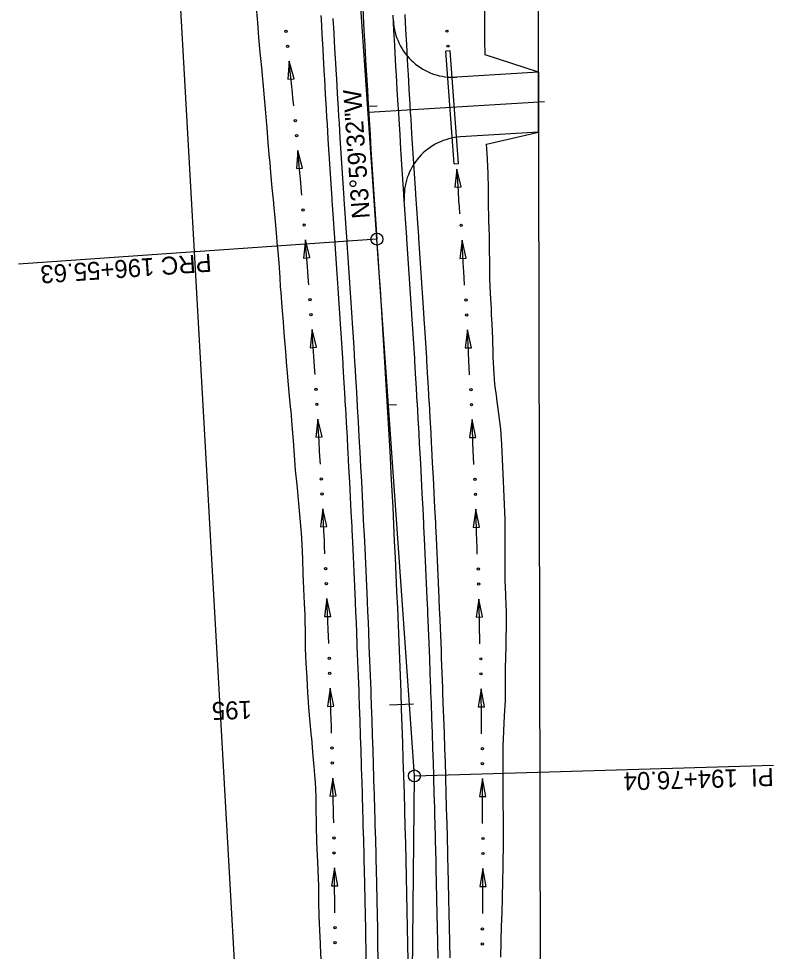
# Model space of a CAD drawing. Extents: x 1 to 1477871, y 1 to 1872901.
# Drawn here: x 1438502.6 to 1438754.8, y 1869354.3 to 1869665.9 of the extents above; entities that cross this region are included whole.
import ezdxf

# ---------------------------------------------------------------- set-up
doc = ezdxf.new("R2010")
doc.units = 0
for name, color, linetype in [('R_Drive', 7, 'Continuous'), ('R_Horz Alg', 7, 'Continuous'), ('R_Horz Alg Annot', 7, 'Continuous'), ('R_No Plot', 7, 'Continuous'), ('R_Proposed Const Limits_Cut', 7, 'Continuous'), ('R_Proposed Road_Lane', 7, 'Continuous'), ('R_Proposed Road_Shoulder', 7, 'Continuous'), ('R_ROW', 7, 'Continuous'), ('R_Water', 7, 'Continuous')]:
    doc.layers.add(name, color=color, linetype=linetype)

msp = doc.modelspace()

# ---------------------------------------------------------------- linework, layer by layer
at = {"layer": 'R_Drive'}
for p, q in [((1438676.27, 1869647.97), (1438648.98, 1869646.32)), ((1438676.27, 1869647.97), (1438676.31, 1869627.94)), ((1438676.31, 1869627.94), (1438650.21, 1869626.36))]:
    msp.add_line(p, q, dxfattribs=at)
for centre, start, end in [((1438647.77, 1869666.28), 183.2722, 273.4625), ((1438651.41, 1869606.39), 93.4625, 183.7812)]:
    msp.add_arc(centre, 20, start, end, dxfattribs=at)
at = {"layer": 'R_Horz Alg'}
for centre, start, end in [((1443194.86, 1869911.35), 180, 183.99213), ((1434049.78, 1869273.13), 359.5, 3.99213)]:
    msp.add_arc(centre, 4583.66, start, end, dxfattribs=at)
at = {"layer": 'R_Horz Alg Annot'}
for p, q in [((1438622.32, 1869592.24), (1438611.19, 1869751.6)), ((1438634.83, 1869412.9), (1438622.32, 1869592.24)), ((1438633.26, 1869233.13), (1438634.83, 1869412.9))]:
    msp.add_line(p, q, dxfattribs=at)
for points in [[(1438622.44, 1869636.7), (1438619.44, 1869636.52)], [(1438622.32, 1869592.24), (1438502.61, 1869583.89)], [(1438628.85, 1869536.9), (1438625.85, 1869536.72)], [(1438626.52, 1869436.69), (1438634.51, 1869436.98)], [(1438634.83, 1869412.9), (1438754.78, 1869416.56)]]:
    msp.add_lwpolyline(points, dxfattribs=at)
for centre in [(1438622.32, 1869592.24), (1438634.83, 1869412.9)]:
    msp.add_circle(centre, 2, dxfattribs=at)
at = {"layer": 'R_No Plot'}
msp.add_line((1438678.33, 1869638.08), (1438619.56, 1869634.52), dxfattribs=at)
at = {"layer": 'R_Proposed Const Limits_Cut'}
for points in [[(1438603.7, 1869351.37), (1438603.47, 1869356.33), (1438603.43, 1869356.98), (1438603.23, 1869361.3), (1438603.03, 1869366.26), (1438602.95, 1869370.71), (1438602.95, 1869371.23), (1438602.86, 1869376.2), (1438602.73, 1869381.16), (1438602.56, 1869384.44), (1438602.47, 1869386.12), (1438602.19, 1869391.09), (1438602.09, 1869396.05), (1438602.08, 1869398.16), (1438602.07, 1869401.02), (1438602.04, 1869405.99), (1438601.75, 1869410.95), (1438601.66, 1869411.89), (1438601.34, 1869415.91), (1438600.95, 1869420.87), (1438600.52, 1869425.59), (1438600.49, 1869425.82), (1438599.99, 1869430.77), (1438599.6, 1869435.73), (1438599.35, 1869439.29), (1438599.27, 1869440.69), (1438599, 1869445.65), (1438598.72, 1869450.61), (1438598.59, 1869453), (1438598.47, 1869455.56), (1438598.4, 1869460.53), (1438598.39, 1869465.5), (1438598.39, 1869466.73), (1438598.17, 1869470.46), (1438597.9, 1869475.42), (1438597.72, 1869480.39), (1438597.71, 1869480.44), (1438597.53, 1869485.35), (1438597.33, 1869490.31), (1438597.08, 1869494.15), (1438596.99, 1869495.27), (1438596.56, 1869500.22), (1438596.1, 1869505.17), (1438595.85, 1869507.84), (1438595.63, 1869510.11), (1438595.15, 1869515.06), (1438594.76, 1869520.01), (1438594.65, 1869521.52), (1438594.4, 1869524.97), (1438594.04, 1869529.92), (1438593.61, 1869534.87), (1438593.58, 1869535.21), (1438593.14, 1869539.81), (1438592.66, 1869544.76), (1438592.3, 1869548.88), (1438592.24, 1869549.71), (1438591.86, 1869554.66), (1438591.47, 1869559.6), (1438591.24, 1869562.56), (1438591.08, 1869564.55), (1438590.69, 1869569.5), (1438590.28, 1869574.45), (1438590.14, 1869576.24), (1438590, 1869579.41), (1438589.66, 1869584.36), (1438589.19, 1869589.3), (1438589.14, 1869589.93), (1438588.73, 1869594.31), (1438588.27, 1869599.33), (1438587.87, 1869603.86), (1438587.83, 1869604.34), (1438587.37, 1869609.36), (1438586.91, 1869614.38), (1438586.6, 1869617.79), (1438586.46, 1869619.4), (1438586.03, 1869624.42), (1438585.6, 1869629.44), (1438585.41, 1869631.74), (1438585.18, 1869634.46), (1438584.75, 1869639.48), (1438584.31, 1869644.5), (1438584.21, 1869645.68), (1438583.85, 1869649.52), (1438583.36, 1869654.54), (1438582.9, 1869659.56), (1438582.89, 1869659.62), (1438582.47, 1869664.58), (1438582.38, 1869665.77), (1438582.07, 1869669.61)], [(1438663.74, 1869352.4), (1438663.85, 1869357.43), (1438663.86, 1869358.1), (1438663.96, 1869362.47), (1438664.12, 1869367.51), (1438664.25, 1869372.02), (1438664.26, 1869372.55), (1438664.39, 1869377.59), (1438664.49, 1869382.63), (1438664.55, 1869385.95), (1438664.58, 1869387.67), (1438664.64, 1869392.71), (1438664.59, 1869397.74), (1438664.56, 1869399.88), (1438664.53, 1869402.78), (1438664.47, 1869407.81), (1438664.48, 1869412.85), (1438664.48, 1869413.8), (1438664.48, 1869417.89), (1438664.48, 1869422.93), (1438664.73, 1869427.74), (1438664.74, 1869427.98), (1438664.99, 1869433.03), (1438665.25, 1869438.08), (1438665.25, 1869441.69), (1438665.25, 1869443.12), (1438665.25, 1869448.16), (1438665.37, 1869453.21), (1438665.47, 1869455.64), (1438665.5, 1869458.25), (1438665.57, 1869463.3), (1438665.58, 1869468.34), (1438665.54, 1869469.59), (1438665.41, 1869473.38), (1438665.22, 1869478.42), (1438665.13, 1869483.46), (1438665.12, 1869483.51), (1438665.16, 1869488.51), (1438665.2, 1869493.55), (1438665.22, 1869497.47), (1438665.17, 1869498.6), (1438664.95, 1869503.63), (1438664.72, 1869508.67), (1438664.59, 1869511.39), (1438664.49, 1869513.7), (1438664.27, 1869518.74), (1438664.03, 1869523.78), (1438663.96, 1869525.31), (1438663.69, 1869528.8), (1438663.03, 1869533.82), (1438662.38, 1869538.83), (1438662.33, 1869539.17), (1438661.67, 1869543.83), (1438661.33, 1869548.86), (1438661.15, 1869553.06), (1438661.13, 1869553.9), (1438661.02, 1869558.94), (1438660.83, 1869563.98), (1438660.65, 1869566.99), (1438660.56, 1869569.01), (1438660.31, 1869574.05), (1438660.06, 1869579.08), (1438660.03, 1869580.91), (1438659.99, 1869584.13), (1438659.93, 1869589.18), (1438659.88, 1869594.23), (1438659.87, 1869594.86), (1438659.73, 1869599.2), (1438659.57, 1869604.16), (1438659.58, 1869608.65), (1438659.58, 1869609.13), (1438659.48, 1869614.09), (1438659.28, 1869619.04), (1438659, 1869622.41), (1438658.88, 1869623.99), (1438676.31, 1869627.94), (1438676.27, 1869647.97), (1438658.5, 1869653.76), (1438658.33, 1869658.71), (1438658.35, 1869663.68), (1438658.35, 1869663.74), (1438658.32, 1869668.64)]]:
    msp.add_lwpolyline(points, dxfattribs=at)
at = {"layer": 'R_Proposed Road_Lane'}
for points in [[(1438622.76, 1869351.69), (1438622.67, 1869356.68), (1438622.66, 1869357.34), (1438622.58, 1869361.67), (1438622.48, 1869366.66), (1438622.39, 1869371.13), (1438622.38, 1869371.65), (1438622.27, 1869376.63), (1438622.15, 1869381.62), (1438622.07, 1869384.92), (1438622.03, 1869386.61), (1438621.9, 1869391.6), (1438621.77, 1869396.58), (1438621.71, 1869398.7), (1438621.63, 1869401.57), (1438621.49, 1869406.56), (1438621.34, 1869411.55), (1438621.31, 1869412.49), (1438621.19, 1869416.53), (1438621.03, 1869421.52), (1438620.87, 1869426.27), (1438620.86, 1869426.51), (1438620.7, 1869431.49), (1438620.52, 1869436.48), (1438620.39, 1869440.06), (1438620.34, 1869441.46), (1438620.15, 1869446.45), (1438619.96, 1869451.43), (1438619.87, 1869453.84), (1438619.76, 1869456.42), (1438619.56, 1869461.4), (1438619.35, 1869466.39), (1438619.3, 1869467.62), (1438619.14, 1869471.37), (1438618.92, 1869476.36), (1438618.7, 1869481.34), (1438618.69, 1869481.4), (1438618.47, 1869486.33), (1438618.23, 1869491.31), (1438618.04, 1869495.17), (1438617.99, 1869496.29), (1438617.74, 1869501.28), (1438617.49, 1869506.26), (1438617.35, 1869508.95), (1438617.24, 1869511.24), (1438616.97, 1869516.22), (1438616.7, 1869521.21), (1438616.62, 1869522.72), (1438616.43, 1869526.19), (1438616.15, 1869531.17), (1438615.87, 1869536.15), (1438615.85, 1869536.49), (1438615.58, 1869541.13), (1438615.28, 1869546.11), (1438615.03, 1869550.26), (1438614.98, 1869551.09), (1438614.68, 1869556.07), (1438614.37, 1869561.05), (1438614.18, 1869564.02), (1438614.05, 1869566.03), (1438613.73, 1869571.01), (1438613.4, 1869575.99), (1438613.28, 1869577.79), (1438613.07, 1869580.96), (1438612.73, 1869585.94), (1438612.38, 1869590.92), (1438612.34, 1869591.54), (1438612.04, 1869595.91), (1438611.7, 1869600.91), (1438611.39, 1869605.43), (1438611.36, 1869605.91), (1438611.03, 1869610.91), (1438610.7, 1869615.91), (1438610.49, 1869619.31), (1438610.39, 1869620.91), (1438610.07, 1869625.92), (1438609.76, 1869630.92), (1438609.62, 1869633.2), (1438609.46, 1869635.92), (1438609.16, 1869640.92), (1438608.87, 1869645.92), (1438608.8, 1869647.1), (1438608.58, 1869650.93), (1438608.3, 1869655.93), (1438608.03, 1869660.93), (1438608.02, 1869660.99), (1438607.75, 1869665.94)], [(1438642.76, 1869352.04), (1438642.67, 1869357.05), (1438642.66, 1869357.71), (1438642.58, 1869362.06), (1438642.48, 1869367.07), (1438642.38, 1869371.55), (1438642.37, 1869372.08), (1438642.26, 1869377.09), (1438642.14, 1869382.1), (1438642.06, 1869385.4), (1438642.02, 1869387.11), (1438641.9, 1869392.11), (1438641.76, 1869397.12), (1438641.71, 1869399.25), (1438641.62, 1869402.13), (1438641.48, 1869407.14), (1438641.33, 1869412.15), (1438641.3, 1869413.1), (1438641.18, 1869417.16), (1438641.02, 1869422.17), (1438640.86, 1869426.94), (1438640.85, 1869427.18), (1438640.68, 1869432.18), (1438640.51, 1869437.19), (1438640.38, 1869440.79), (1438640.32, 1869442.2), (1438640.14, 1869447.21), (1438639.95, 1869452.21), (1438639.85, 1869454.63), (1438639.75, 1869457.22), (1438639.54, 1869462.23), (1438639.33, 1869467.23), (1438639.28, 1869468.47), (1438639.12, 1869472.24), (1438638.9, 1869477.25), (1438638.68, 1869482.25), (1438638.67, 1869482.31), (1438638.44, 1869487.26), (1438638.21, 1869492.26), (1438638.02, 1869496.14), (1438637.97, 1869497.27), (1438637.72, 1869502.27), (1438637.47, 1869507.28), (1438637.33, 1869509.98), (1438637.21, 1869512.28), (1438636.94, 1869517.29), (1438636.68, 1869522.29), (1438636.59, 1869523.81), (1438636.4, 1869527.29), (1438636.12, 1869532.3), (1438635.83, 1869537.3), (1438635.81, 1869537.64), (1438635.54, 1869542.3), (1438635.25, 1869547.3), (1438635, 1869551.47), (1438634.95, 1869552.3), (1438634.64, 1869557.31), (1438634.33, 1869562.31), (1438634.14, 1869565.29), (1438634.01, 1869567.31), (1438633.68, 1869572.31), (1438633.35, 1869577.31), (1438633.24, 1869579.12), (1438633.02, 1869582.31), (1438632.68, 1869587.31), (1438632.33, 1869592.31), (1438632.29, 1869592.94), (1438631.99, 1869597.29), (1438631.65, 1869602.27), (1438631.35, 1869606.76), (1438631.31, 1869607.24), (1438630.99, 1869612.22), (1438630.66, 1869617.2), (1438630.45, 1869620.59), (1438630.34, 1869622.18), (1438630.03, 1869627.16), (1438629.73, 1869632.14), (1438629.59, 1869634.42), (1438629.42, 1869637.12), (1438629.13, 1869642.1), (1438628.83, 1869647.08), (1438628.77, 1869648.25), (1438628.55, 1869652.06), (1438628.27, 1869657.04), (1438628, 1869662.02), (1438627.99, 1869662.08), (1438627.73, 1869667)]]:
    msp.add_lwpolyline(points, dxfattribs=at)
at = {"layer": 'R_Proposed Road_Shoulder'}
for points in [[(1438618.76, 1869351.62), (1438618.67, 1869356.61), (1438618.66, 1869357.26), (1438618.58, 1869361.59), (1438618.48, 1869366.58), (1438618.39, 1869371.04), (1438618.38, 1869371.56), (1438618.27, 1869376.54), (1438618.15, 1869381.53), (1438618.07, 1869384.82), (1438618.03, 1869386.51), (1438617.9, 1869391.49), (1438617.77, 1869396.48), (1438617.71, 1869398.59), (1438617.64, 1869401.46), (1438617.49, 1869406.44), (1438617.34, 1869411.43), (1438617.31, 1869412.37), (1438617.19, 1869416.41), (1438617.03, 1869421.39), (1438616.88, 1869426.14), (1438616.87, 1869426.37), (1438616.7, 1869431.35), (1438616.52, 1869436.33), (1438616.39, 1869439.91), (1438616.34, 1869441.32), (1438616.16, 1869446.3), (1438615.96, 1869451.28), (1438615.87, 1869453.68), (1438615.77, 1869456.26), (1438615.56, 1869461.24), (1438615.36, 1869466.22), (1438615.3, 1869467.45), (1438615.14, 1869471.2), (1438614.92, 1869476.18), (1438614.7, 1869481.16), (1438614.7, 1869481.21), (1438614.47, 1869486.14), (1438614.24, 1869491.12), (1438614.05, 1869494.98), (1438613.99, 1869496.1), (1438613.75, 1869501.08), (1438613.5, 1869506.05), (1438613.36, 1869508.74), (1438613.24, 1869511.03), (1438612.98, 1869516.01), (1438612.71, 1869520.99), (1438612.63, 1869522.5), (1438612.44, 1869525.97), (1438612.16, 1869530.94), (1438611.88, 1869535.92), (1438611.85, 1869536.26), (1438611.58, 1869540.9), (1438611.29, 1869545.87), (1438611.04, 1869550.02), (1438610.99, 1869550.85), (1438610.69, 1869555.82), (1438610.37, 1869560.8), (1438610.19, 1869563.77), (1438610.06, 1869565.77), (1438609.74, 1869570.75), (1438609.41, 1869575.72), (1438609.29, 1869577.52), (1438609.07, 1869580.69), (1438608.74, 1869585.67), (1438608.39, 1869590.64), (1438608.35, 1869591.27), (1438608.05, 1869595.64), (1438607.71, 1869600.64), (1438607.4, 1869605.16), (1438607.37, 1869605.65), (1438607.04, 1869610.65), (1438606.71, 1869615.66), (1438606.49, 1869619.06), (1438606.39, 1869620.66), (1438606.08, 1869625.67), (1438605.77, 1869630.67), (1438605.63, 1869632.96), (1438605.47, 1869635.68), (1438605.17, 1869640.69), (1438604.88, 1869645.69), (1438604.81, 1869646.87), (1438604.59, 1869650.7), (1438604.31, 1869655.71), (1438604.03, 1869660.71), (1438604.03, 1869660.77), (1438603.76, 1869665.72), (1438603.7, 1869666.9)], [(1438646.76, 1869352.11), (1438646.67, 1869357.12), (1438646.66, 1869357.78), (1438646.57, 1869362.14), (1438646.48, 1869367.15), (1438646.38, 1869371.64), (1438646.37, 1869372.16), (1438646.26, 1869377.18), (1438646.14, 1869382.19), (1438646.06, 1869385.5), (1438646.02, 1869387.21), (1438645.89, 1869392.22), (1438645.76, 1869397.23), (1438645.7, 1869399.36), (1438645.62, 1869402.25), (1438645.48, 1869407.26), (1438645.33, 1869412.27), (1438645.3, 1869413.22), (1438645.18, 1869417.29), (1438645.02, 1869422.3), (1438644.86, 1869427.08), (1438644.85, 1869427.31), (1438644.68, 1869432.32), (1438644.5, 1869437.33), (1438644.37, 1869440.93), (1438644.32, 1869442.35), (1438644.14, 1869447.36), (1438643.94, 1869452.37), (1438643.85, 1869454.79), (1438643.74, 1869457.38), (1438643.54, 1869462.39), (1438643.33, 1869467.4), (1438643.28, 1869468.64), (1438643.12, 1869472.41), (1438642.9, 1869477.42), (1438642.67, 1869482.44), (1438642.67, 1869482.49), (1438642.44, 1869487.45), (1438642.2, 1869492.45), (1438642.02, 1869496.34), (1438641.96, 1869497.46), (1438641.71, 1869502.47), (1438641.46, 1869507.48), (1438641.32, 1869510.19), (1438641.2, 1869512.49), (1438640.94, 1869517.5), (1438640.67, 1869522.51), (1438640.59, 1869524.03), (1438640.39, 1869527.51), (1438640.11, 1869532.52), (1438639.83, 1869537.53), (1438639.81, 1869537.87), (1438639.54, 1869542.54), (1438639.24, 1869547.54), (1438638.99, 1869551.71), (1438638.94, 1869552.55), (1438638.63, 1869557.55), (1438638.32, 1869562.56), (1438638.13, 1869565.55), (1438638, 1869567.56), (1438637.68, 1869572.57), (1438637.35, 1869577.57), (1438637.23, 1869579.38), (1438637.01, 1869582.58), (1438636.67, 1869587.58), (1438636.32, 1869592.58), (1438636.28, 1869593.22), (1438635.98, 1869597.56), (1438635.64, 1869602.54), (1438635.34, 1869607.03), (1438635.31, 1869607.51), (1438634.98, 1869612.48), (1438634.65, 1869617.46), (1438634.44, 1869620.84), (1438634.34, 1869622.43), (1438634.02, 1869627.41), (1438633.72, 1869632.38), (1438633.58, 1869634.66), (1438633.42, 1869637.36), (1438633.12, 1869642.33), (1438632.83, 1869647.31), (1438632.76, 1869648.48), (1438632.54, 1869652.29), (1438632.26, 1869657.26), (1438631.99, 1869662.24), (1438631.99, 1869662.3), (1438631.72, 1869667.22)]]:
    msp.add_lwpolyline(points, dxfattribs=at)
at = {"layer": 'R_ROW'}
for p, q in [((1438587.34, 1869127.27), (1438531.34, 1870121.98)), ((1438676.17, 1869699.24), (1438677.33, 1869126.48))]:
    msp.add_line(p, q, dxfattribs=at)
at = {"layer": 'R_Water'}
for p, q in [((1438646.83, 1869655.1), (1438645.33, 1869654.99)), ((1438648.11, 1869617.41), (1438645.33, 1869654.99)), ((1438649.61, 1869617.52), (1438646.83, 1869655.1)), ((1438593.01, 1869651.7), (1438592.56, 1869645.62)), ((1438594.67, 1869645.83), (1438593.01, 1869651.7)), ((1438592.56, 1869645.62), (1438594.67, 1869645.83)), ((1438595.93, 1869621.84), (1438595.39, 1869615.77)), ((1438597.5, 1869615.95), (1438595.93, 1869621.84)), ((1438595.39, 1869615.77), (1438597.5, 1869615.95)), ((1438648.11, 1869617.41), (1438649.61, 1869617.52)), ((1438649.06, 1869615.6), (1438648.39, 1869609.54)), ((1438650.5, 1869609.68), (1438649.06, 1869615.6)), ((1438648.39, 1869609.54), (1438650.5, 1869609.68)), ((1438598.42, 1869591.94), (1438597.82, 1869585.88)), ((1438599.93, 1869586.04), (1438598.42, 1869591.94)), ((1438650.76, 1869591.86), (1438650.03, 1869585.81)), ((1438652.15, 1869585.92), (1438650.76, 1869591.86)), ((1438597.82, 1869585.88), (1438599.93, 1869586.04)), ((1438650.03, 1869585.81), (1438652.15, 1869585.92)), ((1438600.63, 1869562.02), (1438599.98, 1869555.97)), ((1438602.09, 1869556.11), (1438600.63, 1869562.02)), ((1438652.59, 1869561.91), (1438651.8, 1869555.87)), ((1438653.92, 1869555.96), (1438652.59, 1869561.91)), ((1438599.98, 1869555.97), (1438602.09, 1869556.11)), ((1438651.8, 1869555.87), (1438653.92, 1869555.96)), ((1438602.57, 1869532.09), (1438601.86, 1869526.03)), ((1438603.97, 1869526.16), (1438602.57, 1869532.09)), ((1438654.14, 1869531.95), (1438653.3, 1869525.92)), ((1438655.41, 1869525.99), (1438654.14, 1869531.95)), ((1438601.86, 1869526.03), (1438603.97, 1869526.16)), ((1438653.3, 1869525.92), (1438655.41, 1869525.99)), ((1438604.23, 1869502.13), (1438603.47, 1869496.09)), ((1438605.58, 1869496.19), (1438604.23, 1869502.13)), ((1438655.42, 1869501.98), (1438654.52, 1869495.95)), ((1438656.64, 1869496.01), (1438655.42, 1869501.98)), ((1438603.47, 1869496.09), (1438605.58, 1869496.19)), ((1438654.52, 1869495.95), (1438656.64, 1869496.01)), ((1438605.61, 1869472.16), (1438604.79, 1869466.13)), ((1438606.9, 1869466.21), (1438605.61, 1869472.16)), ((1438656.42, 1869471.99), (1438655.47, 1869465.97)), ((1438657.59, 1869466.01), (1438656.42, 1869471.99)), ((1438604.79, 1869466.13), (1438606.9, 1869466.21)), ((1438655.47, 1869465.97), (1438657.59, 1869466.01)), ((1438606.72, 1869442.19), (1438605.84, 1869436.16)), ((1438607.96, 1869436.22), (1438606.72, 1869442.19)), ((1438657.16, 1869442), (1438656.15, 1869435.99)), ((1438658.27, 1869436.01), (1438657.16, 1869442)), ((1438605.84, 1869436.16), (1438607.96, 1869436.22)), ((1438656.15, 1869435.99), (1438658.27, 1869436.01)), ((1438607.54, 1869412.2), (1438606.62, 1869406.18)), ((1438608.73, 1869406.22), (1438607.54, 1869412.2)), ((1438657.61, 1869412), (1438656.55, 1869406)), ((1438658.67, 1869406), (1438657.61, 1869412)), ((1438606.62, 1869406.18), (1438608.73, 1869406.22)), ((1438656.55, 1869406), (1438658.67, 1869406)), ((1438608.1, 1869382.2), (1438607.11, 1869376.19)), ((1438609.23, 1869376.22), (1438608.1, 1869382.2)), ((1438657.75, 1869382), (1438656.66, 1869376.01)), ((1438658.77, 1869376), (1438657.75, 1869382)), ((1438607.11, 1869376.19), (1438609.23, 1869376.22)), ((1438656.66, 1869376.01), (1438658.77, 1869376))]:
    msp.add_line(p, q, dxfattribs=at)
for points in [[(1438594.53, 1869636.77), (1438594.27, 1869639.28), (1438594.08, 1869641.15), (1438593.77, 1869644.24), (1438593.26, 1869649.19), (1438593.01, 1869651.7)], [(1438597.22, 1869606.89), (1438597, 1869609.4), (1438596.84, 1869611.28), (1438596.57, 1869614.37), (1438596.14, 1869619.33), (1438595.93, 1869621.84)], [(1438650.02, 1869600.63), (1438649.86, 1869603.14), (1438649.74, 1869605.02), (1438649.54, 1869608.11), (1438649.22, 1869613.09), (1438649.07, 1869615.6)], [(1438599.57, 1869576.99), (1438599.37, 1869579.5), (1438599.23, 1869581.37), (1438598.99, 1869584.47), (1438598.61, 1869589.43), (1438598.42, 1869591.94)], [(1438651.58, 1869576.88), (1438651.45, 1869579.39), (1438651.34, 1869581.27), (1438651.17, 1869584.37), (1438650.9, 1869589.35), (1438650.77, 1869591.86)], [(1438601.64, 1869547.06), (1438601.47, 1869549.57), (1438601.34, 1869551.45), (1438601.13, 1869554.54), (1438600.8, 1869559.51), (1438600.63, 1869562.02)], [(1438653.27, 1869546.93), (1438653.15, 1869549.44), (1438653.07, 1869551.32), (1438652.93, 1869554.42), (1438652.7, 1869559.4), (1438652.59, 1869561.91)], [(1438603.44, 1869517.11), (1438603.29, 1869519.63), (1438603.18, 1869521.51), (1438603, 1869524.6), (1438602.71, 1869529.58), (1438602.57, 1869532.09)], [(1438654.69, 1869516.96), (1438654.59, 1869519.48), (1438654.52, 1869521.36), (1438654.41, 1869524.46), (1438654.23, 1869529.44), (1438654.14, 1869531.95)], [(1438604.96, 1869487.15), (1438604.84, 1869489.67), (1438604.75, 1869491.55), (1438604.6, 1869494.64), (1438604.35, 1869499.62), (1438604.23, 1869502.13)], [(1438655.83, 1869486.98), (1438655.76, 1869489.5), (1438655.7, 1869491.38), (1438655.62, 1869494.48), (1438655.49, 1869499.46), (1438655.42, 1869501.98)], [(1438606.21, 1869457.18), (1438606.11, 1869459.69), (1438606.03, 1869461.57), (1438605.91, 1869464.67), (1438605.71, 1869469.65), (1438605.61, 1869472.16)], [(1438656.7, 1869456.99), (1438656.65, 1869459.51), (1438656.61, 1869461.4), (1438656.55, 1869464.49), (1438656.46, 1869469.48), (1438656.42, 1869471.99)], [(1438607.18, 1869427.19), (1438607.1, 1869429.71), (1438607.04, 1869431.59), (1438606.94, 1869434.69), (1438606.79, 1869439.67), (1438606.72, 1869442.19)], [(1438657.29, 1869427), (1438657.27, 1869429.52), (1438657.25, 1869431.4), (1438657.22, 1869434.5), (1438657.18, 1869439.49), (1438657.16, 1869442)], [(1438607.87, 1869397.2), (1438607.81, 1869399.72), (1438607.77, 1869401.6), (1438607.71, 1869404.7), (1438607.6, 1869409.68), (1438607.55, 1869412.2)], [(1438657.61, 1869397), (1438657.61, 1869399.52), (1438657.61, 1869401.4), (1438657.61, 1869404.5), (1438657.61, 1869409.49), (1438657.61, 1869412)], [(1438608.28, 1869367.2), (1438608.25, 1869369.72), (1438608.23, 1869371.6), (1438608.19, 1869374.7), (1438608.13, 1869379.69), (1438608.1, 1869382.2)], [(1438657.66, 1869367), (1438657.68, 1869369.52), (1438657.69, 1869371.4), (1438657.71, 1869374.5), (1438657.74, 1869379.49), (1438657.75, 1869382)]]:
    msp.add_lwpolyline(points, dxfattribs=at)
for centre in [(1438591.97, 1869661.66), (1438645.69, 1869661.69), (1438592.47, 1869656.67), (1438646.03, 1869656.69), (1438595.05, 1869631.81), (1438595.47, 1869626.82), (1438597.63, 1869601.93), (1438598, 1869596.93), (1438650.46, 1869596.85), (1438599.93, 1869572.01), (1438652.11, 1869571.92), (1438600.26, 1869567.02), (1438652.33, 1869566.91), (1438601.96, 1869542.08), (1438653.74, 1869541.96), (1438602.24, 1869537.08), (1438653.92, 1869536.95), (1438603.72, 1869512.14), (1438655.12, 1869511.99), (1438603.96, 1869507.13), (1438655.25, 1869506.98), (1438605.18, 1869482.17), (1438656.21, 1869482.01), (1438605.38, 1869477.17), (1438656.29, 1869477), (1438606.38, 1869452.2), (1438657.04, 1869452.02), (1438606.53, 1869447.19), (1438657.08, 1869447.01), (1438607.3, 1869422.21), (1438657.58, 1869422.02), (1438607.41, 1869417.2), (1438657.57, 1869417.01), (1438607.95, 1869392.22), (1438657.78, 1869392.02), (1438608, 1869387.21), (1438657.75, 1869387.01), (1438608.33, 1869362.22), (1438657.56, 1869361.81), (1438608.33, 1869357.21), (1438657.52, 1869356.8)]:
    msp.add_circle(centre, 0.375, dxfattribs=at)

# ---------------------------------------------------------------- texts
at = {"layer": 'R_Horz Alg Annot'}
for s, rotation, p in [('N3%%d59\'32"W', 93.9921, (1438620, 1869599.25)), ('PRC 196+55.63', 183.9921, (1438566.87, 1869587.37)), ('195', 182.0468, (1438580.44, 1869438.05)), ('PI  194+76.04', 181.7461, (1438754.81, 1869415.56))]:
    msp.add_text(s, height=6, rotation=rotation, dxfattribs=at).set_placement(p)

doc.saveas('drawing.dxf')
